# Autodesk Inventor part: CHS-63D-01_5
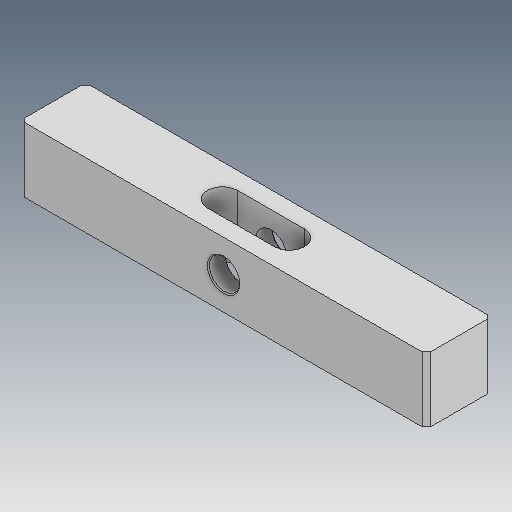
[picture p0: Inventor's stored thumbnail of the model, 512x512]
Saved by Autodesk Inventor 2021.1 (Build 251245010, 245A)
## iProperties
Created: 2019-05
Part Number: CHS-63D-01_5
Material: Ogólny
Document SubType Name: Modeling
Designer: user
Density: 1 g/cm^3
Appearance: Domyślna
Author: user
Revision Number: ÈÎºÎ
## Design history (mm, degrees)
feature "ÊäÈë1"
node "Bryła1"
